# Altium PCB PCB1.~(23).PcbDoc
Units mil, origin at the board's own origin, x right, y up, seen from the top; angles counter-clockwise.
Board outline 1890 x 1900 mil, 2 copper layers (Top Layer, Bottom Layer); 27 components, 29 nets, 115 pads, 6 vias.
Unrouted connection lines stored in the file: 6.
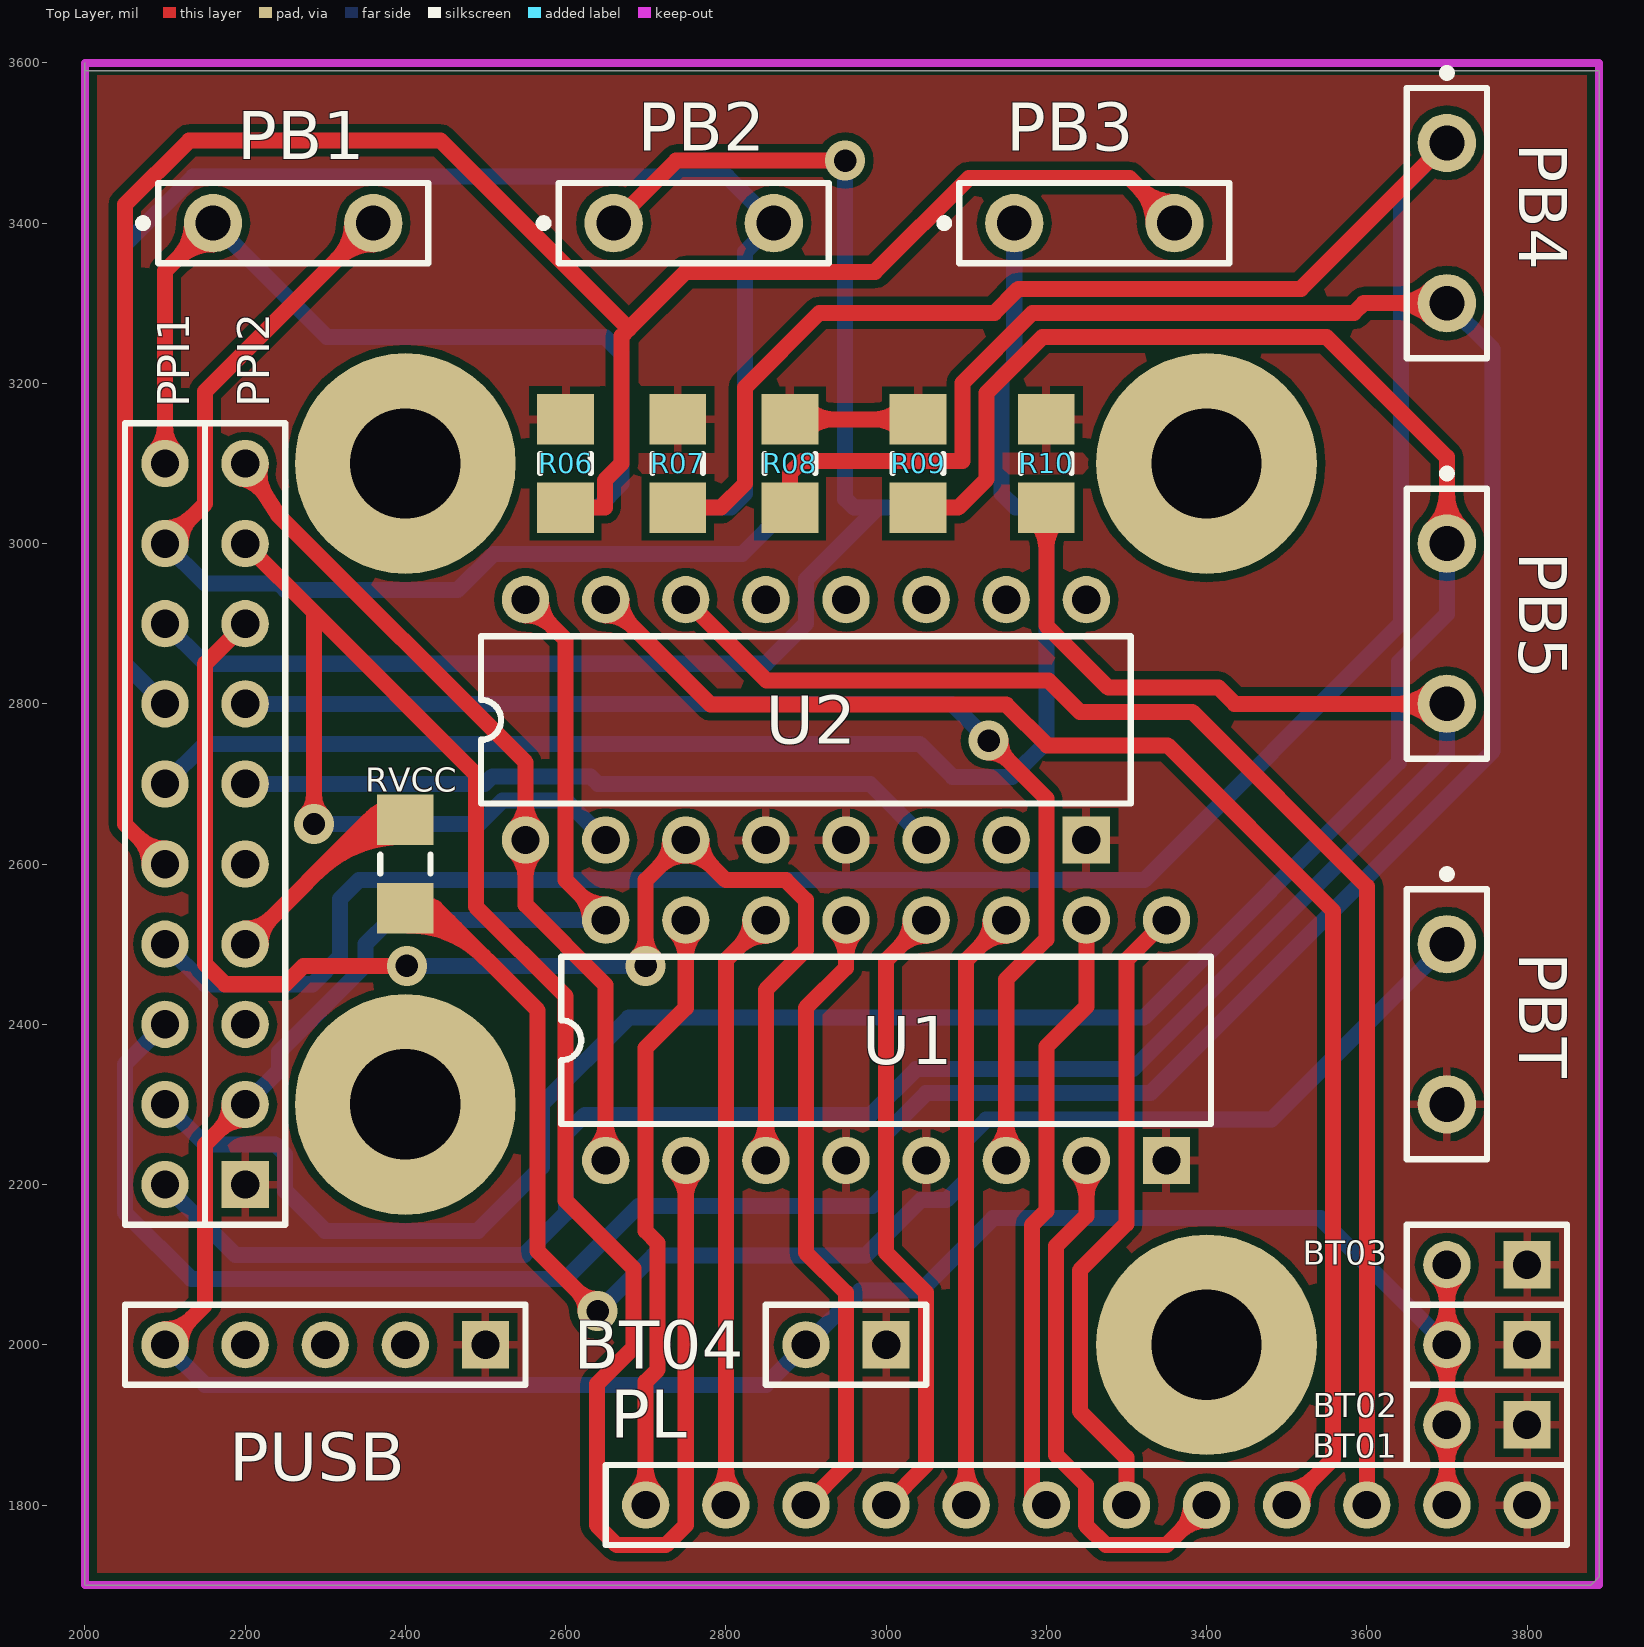
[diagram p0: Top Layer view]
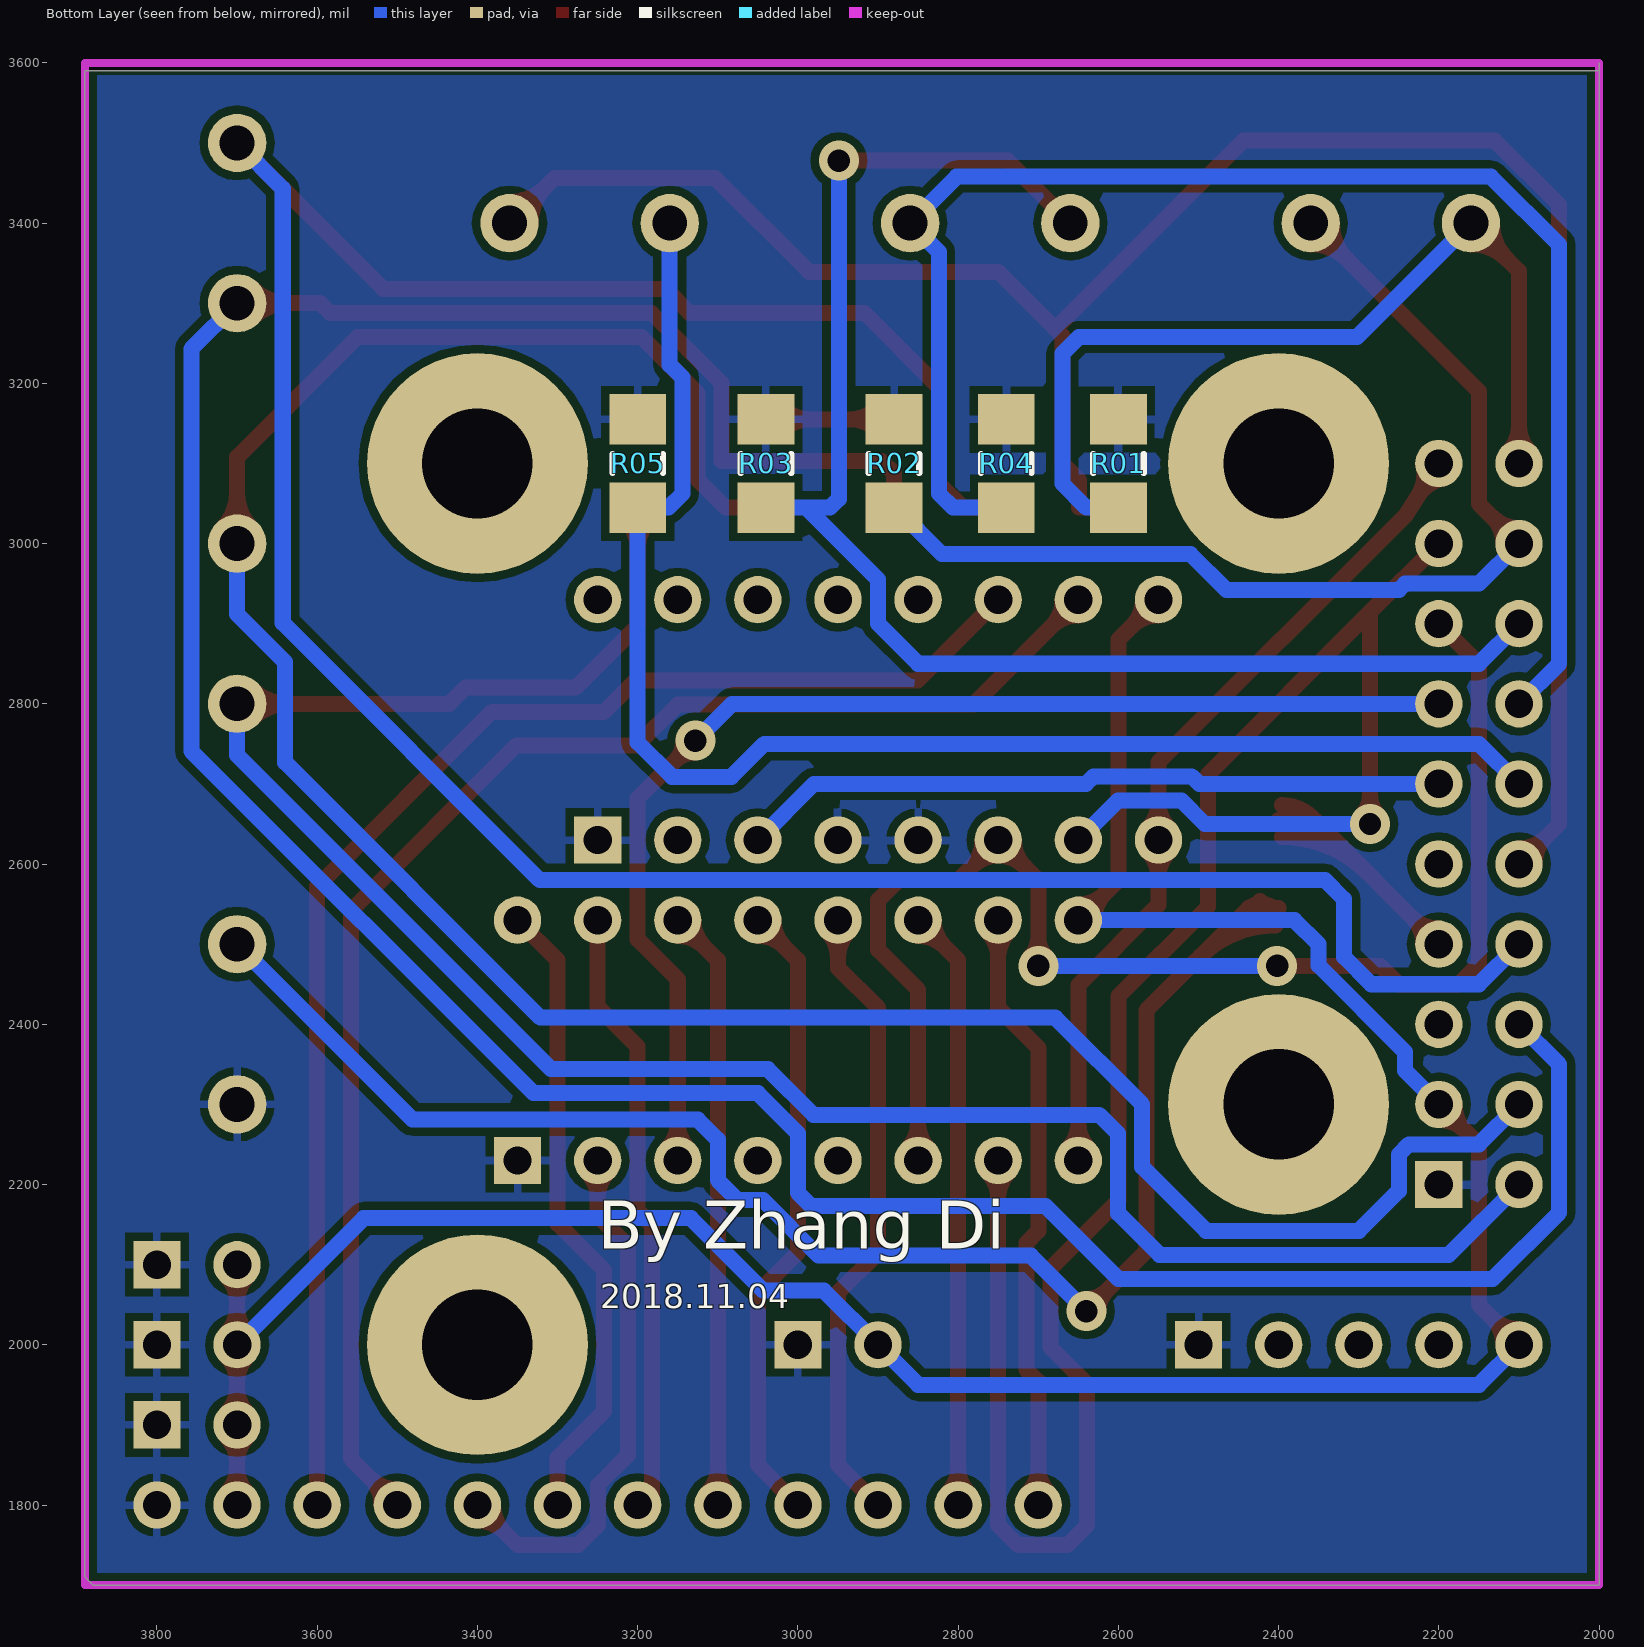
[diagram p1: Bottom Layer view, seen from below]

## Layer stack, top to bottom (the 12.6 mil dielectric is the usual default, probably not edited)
Top Layer: signal copper 1.4
Dielectric: dielectric 12.6, FR-4, Dk 4.8
Bottom Layer: signal copper 1.4

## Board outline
2010,3590 3890,3590 3890,1710 3880,1700 2000,1700 2000,3600 2000,3590

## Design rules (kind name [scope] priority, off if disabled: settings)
Clearance [All] p1: gap=10
ComponentClearance [All] p1: gap=10 collisioncheckmode=3 verticalgap=10
PolygonConnect [All] p1: connectstyle=Relief reliefconductorwidth=10 reliefentries=4 polygonreliefangle="90 Angle"
RoutingVias [All] p1: holewidth=28 width=50 viastyle="Through Hole" minholewidth=28 minwidth=50 maxholewidth=28 maxwidth=50
SolderMaskExpansion [All] p1: expansion=4
TestPointUsage [All] p1: valid=0 allowmultiple=FALSE
Testpoint [All] p1: side=15 testpointundercomponent=TRUE minsize=40 maxsize=100 preferedsize=60 minholesize=0 maxholesize=40 preferedholesize=32 testpointgrid=1 style=1023 order=0123456789
Width Width_2 [All] p1: maxlimit=30 minlimit=15 preferedwidth=20
Width Width_1 [InNet('VCC')] p2: maxlimit=30 minlimit=20 preferedwidth=30
Width [InNet('GND')] p3: maxlimit=30 minlimit=20 preferedwidth=30
18 further rules are at their usual default settings.

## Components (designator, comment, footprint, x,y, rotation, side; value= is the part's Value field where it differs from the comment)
BT01 "Header 2" HDR1X2 3800,1900 r180 top
BT02 "Header 2" HDR1X2 3800,2000 r180 top
BT03 "Header 2" HDR1X2 3800,2100 r180 top
BT04 "Header 2" HDR1X2 3000,2000 r180 top
PB1 "Header 2" SPST-2 2260,3400 r0 top
PB2 "Header 2" SPST-2 2760,3400 r0 top
PB3 "Header 2" SPST-2 3260,3400 r0 top
PB4 "Header 2" SPST-2 3700,3400 r270 top
PB5 "Header 2" SPST-2 3700,2900 r270 top
PBT "Header 2" SPST-2 3700,2400 r270 top
PL "Header 12" HDR1X12 2700,1800 r0 top
PPI1 "Header 10" HDR1X10#1 2100,3100 r270 top
PPI2 "Header 10" HDR1X10#2 2200,3100 r270 top
PUSB "Header 5" HDR1X5 2100,2000 r0 top
R01 "Res1" 3216[1206] 2600,3100 r270 bottom
R02 "Res1" 3216[1206] 2880,3100 r270 bottom
R03 "Res1" 3216[1206] 3040,3100 r270 bottom
R04 "Res1" 3216[1206] 2740,3100 r270 bottom
R05 "Res1" 3216[1206] 3200,3100 r270 bottom
R06 "Res1" 3216[1206] 2600,3100 r270 top
R07 "Res1" 3216[1206] 2740,3100 r270 top
R08 "Res1" 3216[1206] 2880,3100 r270 top
R09 "Res1" 3216[1206] 3040,3100 r270 top
R10 "Res1" 3216[1206] 3200,3100 r270 top
RVCC "Res1" 3216[1206] 2400,2600 r90 top
U1 "SN74HC138D" DIP-16 3000,2380 r0 top
U2 "SN74HC138D" DIP-16 2900,2780 r0 top

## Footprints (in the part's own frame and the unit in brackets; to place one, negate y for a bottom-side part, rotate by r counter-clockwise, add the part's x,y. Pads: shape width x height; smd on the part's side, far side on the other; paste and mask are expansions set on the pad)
3216[1206] [mm] "Chip Resistor; Body 3.2 x 1.6 mm (LxW typ)"
  rect 1.6x1.8 smd: 1(-1.4,0) 2(1.4,0)
  silkscreen extent -0.3,-0.8 0.3,0.8
DIP-16 [mm] "DIP; 16 Leads; Row Spacing 7.62 mm; Pitch 2.54 mm"
  round 1.5 hole 0.9: 1(-8.89,-3.81) 2(-6.35,-3.81) 3(-3.81,-3.81) 4(-1.27,-3.81) 5(1.27,-3.81) 6(3.81,-3.81) 7(6.35,-3.81) 9(8.89,3.81) 10(6.35,3.81) 11(3.81,3.81) 12(1.27,3.81) 13(-1.27,3.81) 14(-3.81,3.81) 15(-6.35,3.81) 16(-8.89,3.81)
  rect 1.5x1.5 hole 0.9: 8(8.89,-3.81)
  silkscreen extent -10.3,-2.65 10.3,2.65
HDR1X2 [mm] "Connector; Header; 2 Position"
  rect 1.5x1.5 hole 0.9: 1(0,0)
  round 1.5 hole 0.9: 2(2.54,0)
  silkscreen extent -1.27,-1.27 3.81,1.27
HDR1X5 [mm] "Connector; Header; 5 Position"
  round 1.5 hole 0.9: 1(0,0) 2(2.54,0) 3(5.08,0) 4(7.62,0)
  rect 1.5x1.5 hole 0.9: 5(10.16,0)
  silkscreen extent -1.27,-1.27 11.43,1.27
HDR1X10#1 [mm] "Connector; Header; 10 Position"
  round 1.5 hole 0.9: 1(0,0) 2(2.54,0) 3(5.08,0) 4(7.62,0) 5(10.16,0) 6(12.7,0) 7(15.24,0) 8(17.78,0) 9(20.32,0) 10(22.86,0)
  silkscreen extent -1.27,-1.27 24.13,1.27
HDR1X10#2 [mm] "Connector; Header; 10 Position"
  round 1.5 hole 0.9: 1(0,0) 2(2.54,0) 3(5.08,0) 4(7.62,0) 5(10.16,0) 6(12.7,0) 7(15.24,0) 8(17.78,0) 9(20.32,0)
  rect 1.5x1.5 hole 0.9: 10(22.86,0)
  silkscreen extent -1.27,-1.27 24.13,1.27
HDR1X12 [mm] "Connector; Header; 12 Position"
  round 1.5 hole 0.9: 1(0,0) 2(2.54,0) 3(5.08,0) 4(7.62,0) 5(10.16,0) 6(12.7,0) 7(15.24,0) 8(17.78,0) 9(20.32,0) 10(22.86,0) 11(25.4,0) 12(27.94,0)
  silkscreen extent -1.27,-1.27 29.21,1.27
SPST-2 [mm] "Circuit Breaker; 2 Leads"
  round 1.85 hole 1.1: 1(-2.54,0) 2(2.54,0)
  silkscreen extent -4.89,-1.27 4.28,1.27

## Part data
BT01 BT02 BT03 BT04 PB1 PB2 PB3 PB4 PB5 PBT: "Header, 2-Pin"
PL: "Header, 12-Pin"
PPI1 PPI2: "Header, 10-Pin"
PUSB: "Header, 5-Pin"
R01 R02 R03 R04 R05 R06 R07 R08 R09 R10 RVCC: "Resistor"
U1 U2: "3-Line to 8-Line Decoder / Demultiplexer"

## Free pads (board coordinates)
  round 275.59 hole 137.8: 0(3400,3100) 1(2400,3100) 3(3400,2000)
  round 275.59 hole 137.8 paste+0: 2(2400,2300)

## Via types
v1: diameter 50, hole 28, Top Layer to Bottom Layer, 6 vias

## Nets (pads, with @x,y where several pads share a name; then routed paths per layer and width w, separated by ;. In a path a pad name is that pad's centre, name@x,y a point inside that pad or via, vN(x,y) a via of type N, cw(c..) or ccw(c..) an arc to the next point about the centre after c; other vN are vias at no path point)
GND: BT01.1 BT02.1 BT03.1 BT04.1 PBT.2 PL.12 PPI2.10 PUSB.5 R01.1 R02.1 R03.1 R04.1 R05.1 R06.1 R07.1 R08.1 R09.1 R10.1 U1.4 U1.5 U1.8 U2.4 U2.5 U2.8 | length 323
  Top Layer w20: R08.1 R09.1 ; R08.1@2899.14,3139.92 cw(c2935.83,3103.22) 2935.83,3155.12 cw(c2935.83,3207.01) R08.1@2899.14,3170.32 ; R09.1@3020.86,3139.92 ccw(c2984.17,3103.22) 2984.17,3155.12 ccw(c2984.17,3207.01) R09.1@3020.86,3170.32
NetPB1_1: PB1.1 PPI1.1 R01.2 | length 1321.1
  Top Layer w20: PPI1.1@2086.19,3113.81 ccw(c2052.86,3147.14) 2100,3147.14 ccw(c2147.14,3147.14) PPI1.1@2113.81,3113.81 ; PPI1.1 2100,3340 PB1.1 ; PB1.1@2133.58,3400 cw(c2069.81,3400) 2114.9,3354.9 cw(c2160,3309.81) PB1.1@2160,3373.58
  Bottom Layer w20: PB1.1 2302,3258 2649,3258 2670,3237 2670,3075 2639.88,3044.88 R01.2
NetPB1_2: PB1.2 PPI1.2 R02.2 | length 1528.4
  Top Layer w20: PPI1.2 2150,3050 2150,3190 PB1.2 ; PPI1.2@2100,3019.53 ccw(c2100,3066.67) 2133.34,3033.34 ccw(c2166.67,3000) PPI1.2@2119.53,3000 ; PB1.2@2333.58,3400 cw(c2269.81,3400) 2314.9,3354.9 cw(c2360,3309.81) PB1.2@2360,3373.58
  Bottom Layer w20: PPI1.2 2150,2950 2242.2,2950 2250,2942.2 2465.36,2942.2 2510.16,2987 2820.21,2987 2878.1,3044.88 R02.2
NetPB2_1: PB2.1 PPI1.3 R03.2 | length 1862.5
  Top Layer w20: PB2.1 2738,3478 v1(2949,3478)
  Bottom Layer w20: PPI1.3 2150,2850 2850,2850 2900,2900 2900,2955 2989.88,3044.88 ; v1(2949,3478) 2949,3055.88 2960,3044.88 2989.88,3044.88 ; R03.2 2989.88,3044.88
NetPB2_2: PB2.2 PPI1.4 R04.2 | length 1906.7
  Bottom Layer w20: PPI1.4 2050,2850 2050,3373 2135,3458 2802,3458 PB2.2 2824,3364 2824,3062.5 2806.38,3044.88 R04.2
NetPB3_1: PB3.1 PPI1.5 R05.2 | length 1856.1
  Bottom Layer w20: PPI1.5 2150,2750 3041.81,2750 3083,2708.81 3157.1,2708.81 3200,2751.71 R05.2 3161.62,3044.88 3144,3062.5 3144,3207 3160,3223 PB3.1
NetPB3_2: PB3.2 PPI1.6 R06.2 | length 2844.4
  Top Layer w20: PPI1.6@2080.47,2600 ccw(c2033.33,2600) 2066.66,2633.34 ccw(c2100,2666.67) PPI1.6@2100,2619.53 ; PPI1.6 2050,2650 2050,3423 2130,3503 2444,3503 2679,3268 ; R06.2 2649,3044.88 2649,3079 2670,3100 2670,3259 2679,3268 ; PB3.2@3333.58,3400 ccw(c3269.81,3400) 3314.9,3445.1 ccw(c3360,3490.19) PB3.2@3360,3426.42 ; PB3.2 3303.58,3456.42 3103.58,3456.42 2986.16,3339 2750,3339 2679,3268
NetPB4_1: PB4.1 PPI1.7 R07.2 | length 3634.3
  Top Layer w20: R07.2 2793.88,3044.88 2824,3075 2824,3195 2916.8,3287.8 3135.18,3287.8 3165.18,3317.8 3517.8,3317.8 PB4.1
  Bottom Layer w20: PPI1.7 2150,2450 2284.41,2450 2318.43,2484.02 2318.43,2556.36 2342.07,2580 3322,2580 3643,2901 3643,3443 PB4.1
NetPB4_2: PB4.2 PPI1.8 R08.2 | length 4003.8
  Top Layer w20: R08.2 2880,3087.5 2895.5,3103 3095.44,3103 3095.44,3200.48 3182.75,3287.8 3584,3287.8 3596.2,3300 PB4.2 ; PB4.2@3681.32,3281.32 ccw(c3636.22,3236.22) 3636.22,3300 ccw(c3636.22,3363.78) PB4.2@3681.32,3318.68
  Bottom Layer w20: PPI1.8 2050,2350 2050,2165 2132.8,2082.2 2600,2082.2 2690.98,2173.19 2983.19,2173.19 3000,2190 3000,2264 3050,2314 3330,2314 3757,2741 3757,3243 PB4.2
NetPB5_1: PB5.1 PPI1.9 R09.2 | length 3298.9
  Top Layer w20: R09.2 3089.88,3044.88 3125.44,3080.44 3125.44,3188.05 3195.18,3257.8 3550,3257.8 3700,3107.8 PB5.1 ; PB5.1@3681.32,3018.68 ccw(c3636.22,3063.78) 3700,3063.78 ccw(c3763.78,3063.78) PB5.1@3718.68,3018.68
  Bottom Layer w20: PPI1.9 2150,2250 2237.5,2250 2250,2237.5 2250,2192.2 2300,2142.2 2490.57,2142.2 2570.47,2222.1 2570.47,2300 2678.83,2408.36 3321.36,2408.36 3640,2727 3640,2852 3700,2912 PB5.1
NetPB5_2: PB5.2 PPI1.10 R10.2 | length 2886.5
  Top Layer w20: R10.2@3184.8,3029.68 cw(c3148.1,2992.99) 3200,2992.99 cw(c3251.9,2992.99) R10.2@3215.2,3029.68 ; R10.2 3200,2897.47 3277.39,2820.08 3415,2820.08 3435.08,2800 PB5.2 ; PB5.2@3681.32,2781.32 ccw(c3636.22,2736.22) 3636.22,2800 ccw(c3636.22,2863.78) PB5.2@3681.32,2818.68
  Bottom Layer w20: PPI1.10 2187.8,2112.2 2548.68,2112.2 2600.47,2164 2600.47,2263.47 2624,2287 2980.57,2287 3037.57,2344 3308,2344 3700,2736 PB5.2
NetPBT_1: PBT.1 RVCC.1 | length 2244.2
  Top Layer w20: RVCC.1 2437.5,2544.88 ; RVCC.1@2403.94,2523.39 cw(c2403.94,2390.46) 2497.93,2484.45 ; RVCC.1@2403.94,2543.39 cw(c2403.94,2458.75) 2463.79,2518.6 ; RVCC.1@2404.94,2543.77 cw(c2421.75,2525.26) 2439.44,2542.94 ; RVCC.1@2418.39,2528.97 cw(c2435.88,2509.7) 2454.28,2528.1 ; RVCC.1@2423.46,2535.89 cw(c2437.5,2529.43) 2437.5,2544.88 ; RVCC.1@2423.46,2553.87 ccw(c2437.5,2560.33) 2437.5,2544.88 ; v1@2625,2042 ccw(c2588.79,2042) 2614.39,2067.61 ccw(c2640,2093.21) v1@2640,2057 ; v1(2640,2042) 2565,2117 2565,2417.38 2437.5,2544.88
  Bottom Layer w20: v1(2640,2042) 2709.32,2111.32 2974.32,2111.32 3043.47,2180.47 3075,2180.47 3100,2205.47 3100,2256 3125,2281 3481,2281 PBT.1
NetPL_1: PL.1 U1.15 | length 911.2
  Top Layer w20: PL.1@2686.19,1813.81 ccw(c2652.86,1847.14) 2700,1847.14 ccw(c2747.14,1847.14) PL.1@2713.81,1813.81 ; PL.1 2700,1954 2715,1969 2715,2127 2700,2142 2700,2370.47 2750,2420.47 U1.15 ; U1.15@2736.19,2516.19 cw(c2702.86,2482.86) 2750,2482.86 cw(c2797.14,2482.86) U1.15@2763.81,2516.19
NetPL_2: PL.2 U1.14 | length 898.8
  Top Layer w20: PL.2@2786.19,1813.81 ccw(c2752.86,1847.14) 2800,1847.14 ccw(c2847.14,1847.14) PL.2@2813.81,1813.81 ; PL.2 2800,2480 U1.14 ; U1.14@2830.47,2530 cw(c2783.33,2530) 2816.66,2496.66 cw(c2850,2463.33) U1.14@2850,2510.47
NetPL_3: PL.3 U1.13 | length 866.2
  Top Layer w20: PL.3 2950,1850 2950,2065 2900,2115 2900,2420.47 2950,2470.47 U1.13 ; U1.13@2936.19,2516.19 cw(c2902.86,2482.86) 2950,2482.86 cw(c2997.14,2482.86) U1.13@2963.81,2516.19
NetPL_4: PL.4 U1.12 | length 866.2
  Top Layer w20: PL.4 3050,1850 3050,2065 3000,2115 3000,2480 U1.12 ; U1.12@3030.47,2530 cw(c2983.33,2530) 3016.66,2496.66 cw(c3050,2463.33) U1.12@3050,2510.47
NetPL_5: PL.5 U1.11 | length 898.8
  Top Layer w20: PL.5@3086.19,1813.81 ccw(c3052.86,1847.14) 3100,1847.14 ccw(c3147.14,1847.14) PL.5@3113.81,1813.81 ; PL.5 3100,2480 U1.11 ; U1.11@3130.47,2530 cw(c3083.33,2530) 3116.66,2496.66 cw(c3150,2463.33) U1.11@3150,2510.47
NetPL_6: PL.6 U1.10 | length 776.2
  Top Layer w20: PL.6 3200,1806.81 3182,1806.81 3182,2149.2 3200,2167.2 3200,2372 3250,2422 U1.10
NetPL_7: PL.7 U1.9 | length 798.8
  Top Layer w20: PL.7 3300,1859.06 3242,1917.06 3242,2093 3300,2151 3300,2480 U1.9
NetPL_8: PL.8 U1.7 | length 815.9
  Top Layer w20: U1.7@3236.19,2216.19 cw(c3202.86,2182.86) 3250,2182.86 cw(c3297.14,2182.86) U1.7@3263.81,2216.19 ; U1.7 3250,2161 3212,2123 3212,1862.53 3249.53,1825 3249.53,1775 3274.53,1750 3350,1750 PL.8 ; PL.8@3380.47,1800 cw(c3333.33,1800) 3366.66,1766.66 cw(c3400,1733.33) PL.8@3400,1780.47
NetPL_9: PL.9 U2.15 | length 1982.5
  Top Layer w20: U2.15@2650,2910.47 cw(c2650,2863.33) 2683.34,2896.66 cw(c2716.67,2930) U2.15@2669.53,2930 ; U2.15 2781,2799 3150,2799 3201,2748 3351.41,2748 3558,2541.41 3558,1858 PL.9 ; PL.9@3500,1819.53 ccw(c3500,1866.67) 3533.34,1833.34 ccw(c3566.67,1800) PL.9@3519.53,1800
NetPL_10: PL.10 U2.14 | length 1770.3
  Top Layer w20: U2.14 2851,2829 3203,2829 3242,2790 3382,2790 3600,2572 PL.10
NetPPI2_1: PPI2.1 U1.1 U2.1 | length 1347.6
  Top Layer w20: PPI2.1@2195.89,3080.91 cw(c2185.97,3034.82) 2225.57,3060.4 cw(c2265.18,3085.97) PPI2.1@2219.09,3095.89 ; PPI2.1 2242.2,3034.64 2550,2726.84 U2.1 2550,2549 2650,2449 U1.1 ; U2.1@2536.19,2616.19 cw(c2502.86,2582.86) 2550,2582.86 cw(c2597.14,2582.86) U2.1@2563.81,2616.19 ; U2.1@2536.19,2643.81 ccw(c2502.86,2677.14) 2550,2677.14 ccw(c2597.14,2677.14) U2.1@2563.81,2643.81 ; U1.1@2636.19,2243.81 ccw(c2602.86,2277.14) 2650,2277.14 ccw(c2697.14,2277.14) U1.1@2663.81,2243.81
NetPPI2_2: PPI2.2 U1.2 U2.2 | length 2823.3
  Top Layer w20: PPI2.2 2286,2914 ; v1@2275.39,2660.61 ccw(c2249.79,2686.21) 2286,2686.21 ccw(c2322.21,2686.21) v1@2296.61,2660.61 ; v1(2286,2650) 2286,2914 ; U1.2@2736.19,2216.19 cw(c2702.86,2182.86) 2750,2182.86 cw(c2797.14,2182.86) U1.2@2763.81,2216.19 ; U1.2 2750,1775 2725,1750 2664,1750 2639,1775 2639,1951 2685,1997 2685,2095 2600,2180 2600,2435 2488,2547 2488,2712 2286,2914
  Bottom Layer w20: v1(2286,2650) 2492,2650 2521.53,2679.53 2600.47,2679.53 U2.2
NetPPI2_3: PPI2.3 U1.3 U2.3 | length 1999.1
  Top Layer w20: PPI2.3 2150,2850 2150,2475 2175,2450 2250,2450 2273,2473 v1(2402,2473) ; v1@2689.39,2483.61 ccw(c2663.79,2509.21) 2700,2509.21 ccw(c2736.21,2509.21) v1@2710.61,2483.61 ; v1(2700,2473) 2700,2580 U2.3 2800,2580 2875,2580 2900,2555 2900,2492.97 2850,2442.97 U1.3 ; U2.3@2730.47,2630 cw(c2683.33,2630) 2716.66,2596.66 cw(c2750,2563.33) 2750,2610.47 cw(c2750,2563.33) 2783.34,2596.66 cw(c2816.67,2630) U2.3@2769.53,2630 ; U1.3@2836.19,2243.81 ccw(c2802.86,2277.14) 2850,2277.14 ccw(c2897.14,2277.14) U1.3@2863.81,2243.81
  Bottom Layer w20: v1(2402,2473) v1(2700,2473)
NetPPI2_4: PPI2.4 U1.6 | length 1652.5
  Top Layer w20: v1@3128,2739 cw(c3128,2702.79) 3153.61,2728.39 cw(c3179.21,2754) v1@3143,2754 ; v1(3128,2754) 3200,2682 3200,2506 3150,2456 U1.6 ; U1.6@3136.19,2243.81 ccw(c3102.86,2277.14) 3150,2277.14 ccw(c3197.14,2277.14) U1.6@3163.81,2243.81
  Bottom Layer w20: PPI2.4 3082,2800 v1(3128,2754)
NetPPI2_5: PPI2.5 U2.6 | length 886.9
  Bottom Layer w20: PPI2.5 2499,2700 2508.53,2709.53 2631,2709.53 2640.6,2699.93 2980.07,2699.93 U2.6
NetPPI2_7: PPI2.7 RVCC.2 | length 735.7
  Top Layer w20: PPI2.7 2355.12,2655.12 ; PPI2.7@2200,2519.53 ccw(c2200,2566.67) 2233.34,2533.34 ccw(c2266.67,2500) PPI2.7@2219.53,2500 ; 2289.47,2589.47 cw(c2396.06,2482.88) RVCC.2@2396.06,2633.62 ; 2323.61,2623.61 cw(c2396.06,2551.16) RVCC.2@2396.06,2653.62 ; 2334.65,2634.65 cw(c2360.78,2608.51) RVCC.2@2383.09,2637.98 ; 2350.88,2650.88 cw(c2374.77,2626.99) RVCC.2@2395.16,2653.93 ; 2357.75,2657.75 cw(c2396.06,2619.44) RVCC.2@2396.06,2673.62 ; RVCC.2@2378.37,2642.91 ccw(c2355.12,2626.87) 2355.12,2655.12 ; RVCC.2@2378.37,2667.32 cw(c2355.12,2683.36) 2355.12,2655.12 ; RVCC.2 2355.12,2655.12
VCC: BT01.2 BT02.2 BT03.2 BT04.2 PL.11 PPI2.9 PUSB.1 U1.16 U2.16 | length 4170.1
  Top Layer w20: PUSB.1 2150,2050 2150,2250 PPI2.9 ; PUSB.1@2100,2019.53 ccw(c2100,2066.67) 2133.34,2033.34 ccw(c2166.67,2000) PUSB.1@2119.53,2000 ; PPI2.9@2180.47,2300 cw(c2133.33,2300) 2166.66,2266.66 cw(c2200,2233.33) PPI2.9@2200,2280.47 ; U2.16@2550,2910.47 cw(c2550,2863.33) 2583.34,2896.66 cw(c2616.67,2930) U2.16@2569.53,2930 ; U2.16 2600,2880 2600,2580 U1.16 ; U1.16@2630.47,2530 ccw(c2583.33,2530) 2616.66,2563.34 ccw(c2650,2596.67) U1.16@2650,2549.53 ; PL.11@3686.19,1813.81 ccw(c3652.86,1847.14) 3700,1847.14 ccw(c3747.14,1847.14) PL.11@3713.81,1813.81 ; BT01.2@3686.19,1886.19 cw(c3652.86,1852.86) 3700,1852.86 cw(c3747.14,1852.86) BT01.2@3713.81,1886.19 ; BT01.2@3686.19,1913.81 ccw(c3652.86,1947.14) 3700,1947.14 ccw(c3747.14,1947.14) BT01.2@3713.81,1913.81 ; BT02.2@3686.19,1986.19 cw(c3652.86,1952.86) 3700,1952.86 cw(c3747.14,1952.86) BT02.2@3713.81,1986.19 ; BT02.2@3686.19,2013.81 ccw(c3652.86,2047.14) 3700,2047.14 ccw(c3747.14,2047.14) BT02.2@3713.81,2013.81 ; BT03.2@3686.19,2086.19 cw(c3652.86,2052.86) 3700,2052.86 cw(c3747.14,2052.86) BT03.2@3713.81,2086.19 ; PL.11 BT01.2 BT02.2 BT03.2
  Bottom Layer w20: PUSB.1 2150,1950 2850,1950 BT04.2 2967.7,2067.7 3043.4,2067.7 3133.7,2158 3542,2158 BT02.2 ; PPI2.9 2242.2,2342.2 2242.2,2365.36 2350.24,2473.4 2350.24,2500 2380.24,2530 U1.16
pads on no net: PPI2.6 PPI2.8 PUSB.2 PUSB.3 PUSB.4 U2.7 U2.9 U2.10 U2.11 U2.12 U2.13

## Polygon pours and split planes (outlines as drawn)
GND on Top Layer "Top Layer-No Net" (solid, remove dead copper): 2000,3600 2000,1700 3890,1700 3890,3600 2000,3600
GND on Bottom Layer "Top Layer-No Net" (solid, remove dead copper): 2010,3600 2010,1700 3900,1700 3900,3590 3890,3600 2010,3600

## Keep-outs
Keep-Out Layer:
  lines w10: 2000,1700 2000,3600 3890,3600 3890,1700 2000,1700

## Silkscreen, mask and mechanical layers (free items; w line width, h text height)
Bottom Overlay:
  text "By Zhang Di" at 3250,2120 h60
  text "2018.11.04" at 3246.65,2045.81 h30
Mechanical 1:
  lines w10: 2000,1700 2000,3600 3890,3600 3890,1710 2010,1710 2000,1700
